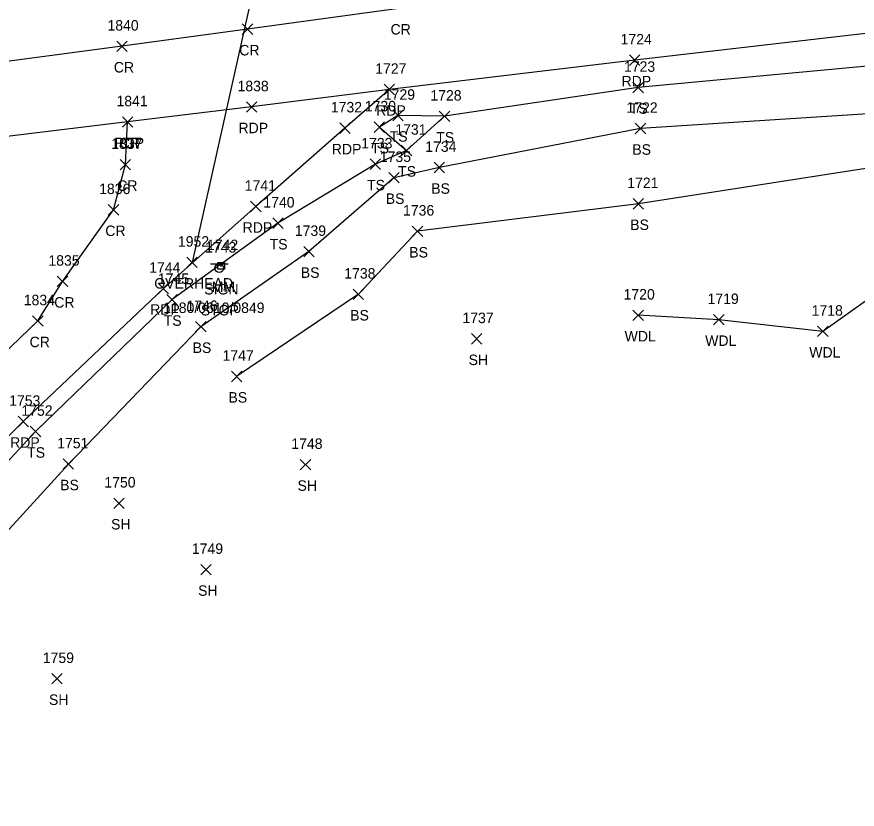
# Model space of a CAD drawing. Extents: x 1600395 to 1603269, y 874955 to 877143.
# Drawn here: x 1601910.3 to 1602070.6, y 875112.5 to 875263.7 of the extents above; entities that cross this region are included whole.
import ezdxf

# ---------------------------------------------------------------- set-up
doc = ezdxf.new("R2010")
doc.units = 0
for name, color, linetype in [('L_A', 7, 'Continuous'), ('L_I', 7, 'Continuous'), ('L_TIC', 7, 'Continuous'), ('LAWA', 7, 'Continuous'), ('LELB', 7, 'Continuous'), ('P_A', 7, 'Continuous'), ('P_I', 7, 'Continuous'), ('P_TIC', 7, 'Continuous'), ('PET', 7, 'Continuous'), ('PRC', 7, 'Continuous'), ('S_A', 7, 'Continuous'), ('S_C', 7, 'Continuous'), ('S_I', 7, 'Continuous'), ('SRM', 7, 'Continuous'), ('SSGN', 7, 'Continuous'), ('U_A', 7, 'Continuous'), ('U_I', 7, 'Continuous'), ('U_TIC', 7, 'Continuous'), ('UCO', 7, 'Continuous')]:
    doc.layers.add(name, color=color, linetype=linetype)

msp = doc.modelspace()

# ---------------------------------------------------------------- linework, layer by layer
at = {"layer": 'L_TIC'}
for points in [[(1602027.81, 875249.19), (1602029.81, 875251.19)], [(1602029.81, 875249.19), (1602027.81, 875251.19)], [(1601982.01, 875243.86), (1601984.01, 875245.86)], [(1601984.01, 875243.86), (1601982.01, 875245.86)], [(1601990.89, 875243.7), (1601992.89, 875245.7)], [(1601992.89, 875243.7), (1601990.89, 875245.7)], [(1601990.89, 875243.7), (1601992.89, 875245.7)], [(1601992.89, 875243.7), (1601990.89, 875245.7)], [(1601978.46, 875241.64), (1601980.46, 875243.64)], [(1601980.46, 875241.64), (1601978.46, 875243.64)], [(1602028.27, 875241.37), (1602030.27, 875243.37)], [(1602030.27, 875241.37), (1602028.27, 875243.37)], [(1601983.63, 875237.19), (1601985.63, 875239.19)], [(1601985.63, 875237.19), (1601983.63, 875239.19)], [(1601983.63, 875237.19), (1601985.63, 875239.19)], [(1601985.63, 875237.19), (1601983.63, 875239.19)], [(1601977.7, 875234.57), (1601979.7, 875236.57)], [(1601979.7, 875234.57), (1601977.7, 875236.57)], [(1601989.91, 875233.92), (1601991.91, 875235.92)], [(1601991.91, 875233.92), (1601989.91, 875235.92)], [(1601981.23, 875231.99), (1601983.23, 875233.99)], [(1601983.23, 875231.99), (1601981.23, 875233.99)], [(1602027.87, 875227.01), (1602029.87, 875229.01)], [(1602029.87, 875227.01), (1602027.87, 875229.01)], [(1601959.11, 875223.3), (1601961.11, 875225.3)], [(1601961.11, 875223.3), (1601959.11, 875225.3)], [(1601985.72, 875221.76), (1601987.72, 875223.76)], [(1601987.72, 875221.76), (1601985.72, 875223.76)], [(1601965.03, 875217.88), (1601967.03, 875219.88)], [(1601967.03, 875217.88), (1601965.03, 875219.88)], [(1601938.91, 875208.73), (1601940.91, 875210.73)], [(1601940.91, 875208.73), (1601938.91, 875210.73)], [(1601974.45, 875209.74), (1601976.45, 875211.74)], [(1601976.45, 875209.74), (1601974.45, 875211.74)], [(1602027.82, 875205.74), (1602029.82, 875207.74)], [(1602029.82, 875205.74), (1602027.82, 875207.74)], [(1601944.4, 875203.55), (1601946.4, 875205.55)], [(1601946.4, 875203.55), (1601944.4, 875205.55)], [(1602043.2, 875204.89), (1602045.2, 875206.89)], [(1602045.2, 875204.89), (1602043.2, 875206.89)], [(1602063.04, 875202.66), (1602065.04, 875204.66)], [(1602065.04, 875202.66), (1602063.04, 875204.66)], [(1601997, 875201.24), (1601999, 875203.24)], [(1601999, 875201.24), (1601997, 875203.24)], [(1601951.23, 875194.07), (1601953.23, 875196.07)], [(1601953.23, 875194.07), (1601951.23, 875196.07)], [(1601912.86, 875183.56), (1601914.86, 875185.56)], [(1601914.86, 875183.56), (1601912.86, 875185.56)], [(1601919.13, 875177.35), (1601921.13, 875179.35)], [(1601921.13, 875177.35), (1601919.13, 875179.35)], [(1601964.36, 875177.24), (1601966.36, 875179.24)], [(1601966.36, 875177.24), (1601964.36, 875179.24)], [(1601928.78, 875169.87), (1601930.78, 875171.87)], [(1601930.78, 875169.87), (1601928.78, 875171.87)], [(1601945.39, 875157.21), (1601947.39, 875159.21)], [(1601947.39, 875157.21), (1601945.39, 875159.21)], [(1601916.95, 875136.39), (1601918.95, 875138.39)], [(1601918.95, 875136.39), (1601916.95, 875138.39)]]:
    msp.add_lwpolyline(points, dxfattribs=at)
at = {"layer": 'LAWA'}
msp.add_lwpolyline([(1602170.27, 875244.78), (1602133.76, 875242.94), (1602110.66, 875236.79), (1602064.04, 875203.66), (1602044.2, 875205.89), (1602028.82, 875206.74)], dxfattribs=at)
at = {"layer": 'LELB'}
for points in [[(1602178.37, 875249.14), (1602177.41, 875259.28), (1602168.51, 875260), (1602131.87, 875260.27), (1602108.92, 875258.18), (1602075.25, 875254.52), (1602028.81, 875250.19), (1601991.89, 875244.7), (1601984.63, 875238.19), (1601978.7, 875235.57), (1601960.11, 875224.3), (1601939.91, 875209.73), (1601913.86, 875184.56), (1601890.29, 875159.09), (1601878.53, 875149.19), (1601876.37, 875148.08), (1601869.76, 875141.55), (1601836.04, 875101.25), (1601811.3, 875055.59)], [(1602174.83, 875251.59), (1602174.74, 875253.75), (1602168.06, 875255.41), (1602131.89, 875251.44), (1602109.84, 875249.62), (1602074.67, 875245.33), (1602029.27, 875242.37), (1601990.91, 875234.92), (1601982.23, 875232.99), (1601966.03, 875218.88), (1601945.4, 875204.55), (1601920.13, 875178.35), (1601896.83, 875152.83)], [(1602174.83, 875251.59), (1602167.46, 875251.04), (1602132.04, 875249.48), (1602108.48, 875244.49), (1602075.92, 875235.34), (1602028.87, 875228.01), (1601986.72, 875222.76), (1601975.45, 875210.74), (1601952.23, 875195.07)], [(1601991.89, 875244.7), (1601983.01, 875244.86), (1601979.46, 875242.64), (1601984.63, 875238.19)]]:
    msp.add_lwpolyline(points, dxfattribs=at)
at = {"layer": 'P_TIC'}
for points in [[(1601953.29, 875260.32), (1601955.29, 875262.32)], [(1601955.29, 875260.32), (1601953.29, 875262.32)], [(1601929.37, 875257.06), (1601931.37, 875259.06)], [(1601931.37, 875257.06), (1601929.37, 875259.06)], [(1602027.17, 875254.41), (1602029.17, 875256.41)], [(1602029.17, 875254.41), (1602027.17, 875256.41)], [(1601980.36, 875248.81), (1601982.36, 875250.81)], [(1601982.36, 875248.81), (1601980.36, 875250.81)], [(1601980.36, 875248.81), (1601982.36, 875250.81)], [(1601982.36, 875248.81), (1601980.36, 875250.81)], [(1601954.09, 875245.48), (1601956.09, 875247.48)], [(1601956.09, 875245.48), (1601954.09, 875247.48)], [(1601930.43, 875242.62), (1601932.43, 875244.62)], [(1601932.43, 875242.62), (1601930.43, 875244.62)], [(1601930.43, 875242.62), (1601932.43, 875244.62)], [(1601932.43, 875242.62), (1601930.43, 875244.62)], [(1601971.89, 875241.44), (1601973.89, 875243.44)], [(1601973.89, 875241.44), (1601971.89, 875243.44)], [(1601930, 875234.48), (1601932, 875236.48)], [(1601932, 875234.48), (1601930, 875236.48)], [(1601927.75, 875225.86), (1601929.75, 875227.86)], [(1601929.75, 875225.86), (1601927.75, 875227.86)], [(1601954.9, 875226.49), (1601956.9, 875228.49)], [(1601956.9, 875226.49), (1601954.9, 875228.49)], [(1601918.01, 875212.2), (1601920.01, 875214.2)], [(1601920.01, 875212.2), (1601918.01, 875214.2)], [(1601937.25, 875210.84), (1601939.25, 875212.84)], [(1601939.25, 875210.84), (1601937.25, 875212.84)], [(1601913.31, 875204.65), (1601915.31, 875206.65)], [(1601915.31, 875204.65), (1601913.31, 875206.65)], [(1601910.53, 875185.46), (1601912.53, 875187.46)], [(1601912.53, 875185.46), (1601910.53, 875187.46)]]:
    msp.add_lwpolyline(points, dxfattribs=at)
at = {"layer": 'PET'}
for points in [[(1602402.41, 875260.95), (1602358.59, 875263.43), (1602318.28, 875265.46), (1602288.26, 875266.89), (1602257.66, 875267.67), (1602209.91, 875267.9), (1602168.76, 875266.82), (1602131.43, 875265.02), (1602108.25, 875263.66), (1602076.07, 875260.92), (1602028.17, 875255.41), (1601981.36, 875249.81), (1601955.09, 875246.48), (1601931.43, 875243.62), (1601904.73, 875240.41), (1601882.14, 875236.79), (1601873.56, 875235.88), (1601879.64, 875251.36), (1601886.39, 875267.75)], [(1601981.36, 875249.81), (1601972.89, 875242.44), (1601955.9, 875227.49), (1601938.25, 875211.84), (1601911.53, 875186.46), (1601887.52, 875162.64), (1601873.65, 875148.4), (1601834.56, 875104.33), (1601817.9, 875080.13), (1601806.17, 875058.57), (1601796.42, 875036.34), (1601789.6, 875012.3), (1601785.9, 874989.71)]]:
    msp.add_lwpolyline(points, dxfattribs=at)
at = {"layer": 'PRC'}
for points in [[(1602402.71, 875276.76), (1602360.41, 875278.94), (1602318.06, 875280.96), (1602289.17, 875282.16), (1602257.66, 875282.81), (1602210.34, 875283), (1602169.35, 875282.18), (1602129.85, 875280.43), (1602107.17, 875278.74), (1602075.28, 875276.04), (1602025.43, 875270.72), (1601983.16, 875265.3), (1601954.29, 875261.32), (1601930.37, 875258.06), (1601901.66, 875254.25), (1601879.64, 875251.36)], [(1601775.55, 874992.02), (1601780.37, 875017.6), (1601787.98, 875044.4), (1601800.4, 875072.62), (1601818.14, 875100.61), (1601837.01, 875125.1), (1601855.24, 875145.38), (1601891.25, 875181.43), (1601904.02, 875195.8), (1601914.31, 875205.65), (1601919.01, 875213.2), (1601928.75, 875226.86), (1601931, 875235.48), (1601931.43, 875243.62)]]:
    msp.add_lwpolyline(points, dxfattribs=at)
at = {"layer": 'SRM'}
msp.add_lwpolyline([(1601948.65, 875216.79), (1601949.9, 875216.79), (1601949.9, 875215.54), (1601948.65, 875215.54)], close=True, dxfattribs=at)
msp.add_circle((1601949.28, 875216.17), 0.0833, dxfattribs=at)
at = {"layer": 'SSGN'}
for p, q in [((1601947.27, 875216.56), (1601950.6, 875216.56)), ((1601948.92, 875215.73), (1601948.92, 875215.73))]:
    msp.add_line(p, q, dxfattribs=at)
msp.add_circle((1601948.92, 875215.73), 0.833, dxfattribs=at)
at = {"layer": 'U_TIC'}
for points in [[(1601942.72, 875215.83), (1601944.72, 875217.83)], [(1601944.72, 875215.83), (1601942.72, 875217.83)]]:
    msp.add_lwpolyline(points, dxfattribs=at)
at = {"layer": 'UCO'}
msp.add_lwpolyline([(1601957.01, 875276.33), (1601943.72, 875216.83)], dxfattribs=at)

# ---------------------------------------------------------------- texts
at = {"layer": 'L_A'}
for s, p in [('TS', (1602027.22, 875245.19)), ('TS', (1601981.42, 875239.86)), ('TS', (1601990.3, 875239.7)), ('TS', (1601990.3, 875239.7)), ('TS', (1601977.87, 875237.64)), ('BS', (1602027.71, 875237.37)), ('TS', (1601983.04, 875233.19)), ('TS', (1601983.04, 875233.19)), ('TS', (1601977.11, 875230.57)), ('BS', (1601989.35, 875229.92)), ('BS', (1601980.67, 875227.99)), ('BS', (1602027.31, 875223.01)), ('TS', (1601958.52, 875219.3)), ('BS', (1601985.16, 875217.76)), ('BS', (1601964.47, 875213.88)), ('BS', (1601973.89, 875205.74)), ('TS', (1601938.32, 875204.73)), ('WDL', (1602026.24, 875201.74)), ('WDL', (1602041.61, 875200.89)), ('BS', (1601943.84, 875199.55)), ('WDL', (1602061.46, 875198.66)), ('SH', (1601996.49, 875197.24)), ('BS', (1601950.67, 875190.07)), ('TS', (1601912.27, 875179.56)), ('BS', (1601918.57, 875173.35)), ('SH', (1601963.84, 875173.24)), ('SH', (1601928.27, 875165.87)), ('SH', (1601944.88, 875153.21)), ('SH', (1601916.44, 875132.39))]:
    msp.add_text(s, height=2, dxfattribs=at).set_placement(p)
at = {"layer": 'L_I'}
for s, p in [('1723', (1602026.12, 875253.19)), ('1729', (1601980.31, 875247.86)), ('1728', (1601989.19, 875247.7)), ('1728', (1601989.19, 875247.7)), ('1730', (1601976.68, 875245.64)), ('1722', (1602026.58, 875245.37)), ('1731', (1601982.5, 875241.19)), ('1731', (1601982.5, 875241.19)), ('1733', (1601976.01, 875238.57)), ('1734', (1601988.21, 875237.92)), ('1735', (1601979.54, 875235.99)), ('1721', (1602026.75, 875231.01)), ('1740', (1601957.33, 875227.3)), ('1736', (1601983.97, 875225.76)), ('1739', (1601963.33, 875221.88)), ('1738', (1601972.76, 875213.74)), ('1745', (1601937.22, 875212.73)), ('1720', (1602026.04, 875209.74)), ('1719', (1602042.06, 875208.89)), ('1746', (1601942.65, 875207.55)), ('1718', (1602061.92, 875206.66)), ('1737', (1601995.3, 875205.24)), ('1747', (1601949.54, 875198.07)), ('1752', (1601911.17, 875187.56)), ('1751', (1601918, 875181.35)), ('1748', (1601962.66, 875181.24)), ('1750', (1601927, 875173.87)), ('1749', (1601943.69, 875161.21)), ('1759', (1601915.25, 875140.39))]:
    msp.add_text(s, height=2, dxfattribs=at).set_placement(p)
at = {"layer": 'P_A'}
for s, p in [('CR', (1601981.59, 875260.3)), ('CR', (1601952.73, 875256.32)), ('CR', (1601928.8, 875253.06)), ('RDP', (1602025.66, 875250.41)), ('RDP', (1601978.85, 875244.81)), ('RDP', (1601978.85, 875244.81)), ('RDP', (1601952.58, 875241.48)), ('RDP', (1601928.92, 875238.62)), ('CR', (1601929.87, 875238.62)), ('RDP', (1601970.38, 875237.44)), ('CR', (1601929.44, 875230.48)), ('CR', (1601927.18, 875221.86)), ('RDP', (1601953.38, 875222.49)), ('CR', (1601917.44, 875208.2)), ('RDP', (1601935.74, 875206.84)), ('CR', (1601912.74, 875200.65)), ('RDP', (1601909.02, 875181.46))]:
    msp.add_text(s, height=2, dxfattribs=at).set_placement(p)
at = {"layer": 'P_I'}
for s, p in [('1840', (1601927.59, 875261.06)), ('1724', (1602025.48, 875258.41)), ('1727', (1601978.67, 875252.81)), ('1727', (1601978.67, 875252.81)), ('1838', (1601952.4, 875249.48)), ('1841', (1601929.31, 875246.62)), ('1841', (1601929.31, 875246.62)), ('1732', (1601970.2, 875245.44)), ('1837', (1601928.31, 875238.48)), ('1836', (1601926, 875229.86)), ('1741', (1601953.77, 875230.49)), ('1835', (1601916.32, 875216.2)), ('1744', (1601935.55, 875214.84)), ('1834', (1601911.62, 875208.65)), ('1753', (1601908.84, 875189.46))]:
    msp.add_text(s, height=2, dxfattribs=at).set_placement(p)
at = {"layer": 'S_A'}
for s, p in [('SIGN', (1601946.06, 875210.71)), ('MM', (1601947.47, 875211.17))]:
    msp.add_text(s, height=2, dxfattribs=at).set_placement(p)
at = {"layer": 'S_C'}
for s, p in [('1180/0610/0849', (1601938.21, 875207.17)), ('STOP', (1601945.38, 875206.71))]:
    msp.add_text(s, height=2, dxfattribs=at).set_placement(p)
at = {"layer": 'S_I'}
for s, p in [('1743', (1601946.21, 875218.71)), ('1742', (1601946.58, 875219.17))]:
    msp.add_text(s, height=2, dxfattribs=at).set_placement(p)
at = {"layer": 'U_A'}
msp.add_text('OVERHEAD', height=2, dxfattribs=at).set_placement((1601936.53, 875211.83))
at = {"layer": 'U_I'}
msp.add_text('1952', height=2, dxfattribs=at).set_placement((1601941.03, 875219.83))

doc.saveas('drawing.dxf')
